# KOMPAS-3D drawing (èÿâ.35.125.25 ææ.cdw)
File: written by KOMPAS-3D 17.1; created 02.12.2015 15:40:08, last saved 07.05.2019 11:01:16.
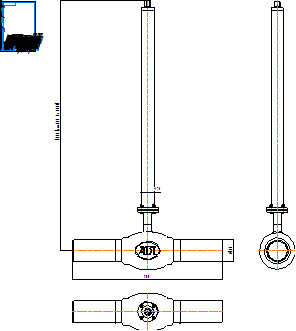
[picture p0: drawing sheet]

Sheet 1: A4, portrait

Title block, sheet 1: name: КШГ.35.125.25 СС; material: Внимание! Данный продукт является объектом авторского права ООО «Торговый Дом АДЛ». / Запрещается изменение, копирование, распространение / (в том числе путем копирования на другие сайты и ресурсы в Интернете) / или любое иное использование информации и объектов без предварительного / согласия правообладателя (ООО «Торговый Дом АДЛ»).; sheets: 1; organisation: ООО "Торговый дом АДЛ"; sheet format: A4; stored path: C:\Users\kka\KOMPAS_Work\Модели кранов для исследований\DN50\С удлинением\КШГ.32.050.40 СС ГЧ _ Шаровой кран БИВАЛ Ду50 Ру4 МПа редуцированный под приварку, с удлинением штока H=1100.cdw; drawn by: Климкович К.А.; drawn by, date: 07.12.16

Views: Вид 1, Проекционный вид 2
Referenced files in C:\Users\kka\KOMPAS_Work\Модели кранов для исследований\DN80\С удлинением\: КШТ.22.080.25 СС.a3d
Referenced files in C:\Users\kka\KOMPAS_Work\Модели кранов для исследований\DN150\С удлинением\: КШТ.22.150.25 СС.a3d, КШГ.35.125.25 СС Lстр600.a3d, КШГ.35.125.25 СС Lстр600.a3d!Деталь (локальная).m3d
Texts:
  Klimkovich
  ADL
  (от 480 до 5000)
Dimensions and other numbers on the sheet: 900; 76; 133; 1500; 1:1; 1; 07.12.16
